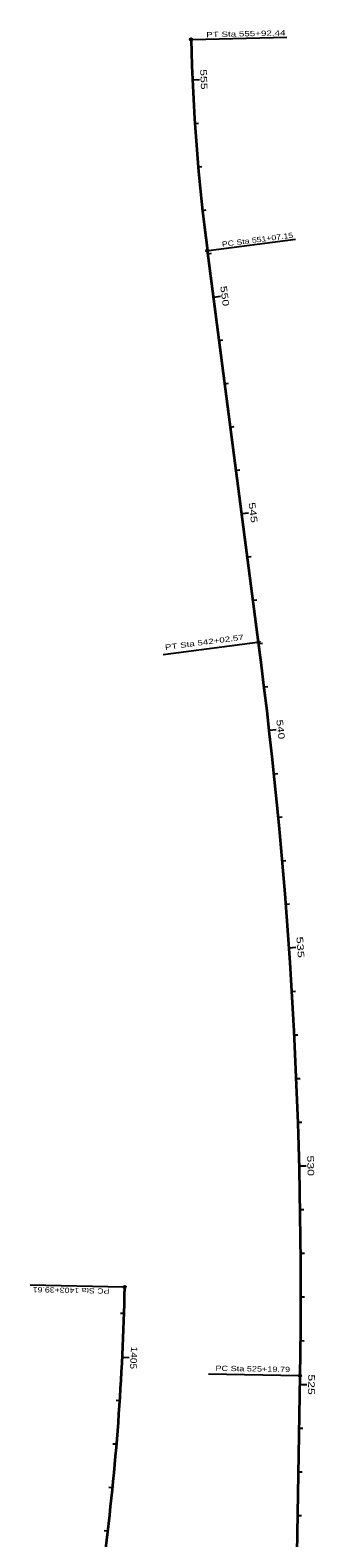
# Model space of a CAD drawing. Extents: x 771045 to 775849, y 632284 to 641017.
# Drawn here: x 772467 to 773120, y 637565 to 641017 of the extents above; entities that cross this region are included whole.
import ezdxf
from ezdxf.enums import TextEntityAlignment as Align

# ---------------------------------------------------------------- set-up
doc = ezdxf.new("R2010")
doc.units = 0
doc.header["$LTSCALE"] = 4.8
for name, color, linetype, lineweight in [('1', 7, 'Continuous', 35), ('30', 7, 'Continuous', 25), ('33', 7, 'Continuous', 25)]:
    doc.layers.add(name, color=color, linetype=linetype, lineweight=lineweight)

msp = doc.modelspace()

# ---------------------------------------------------------------- linework, layer by layer
at = {"layer": '1'}
msp.add_line((772990.84, 639614.773), (772873.465, 640511.706), dxfattribs=at)
msp.add_lwpolyline([(773099.539, 637303.776), (773075.542, 637304.177), (773086.114, 637936.209)], dxfattribs=at)
for centre, radius, start, end in [((777418.376, 641106.467), 4583.662, 181.38943, 187.45554), ((761628.561, 638127.87), 11459.156, 359.04165, 7.45554), ((766955.847, 638255.612), 5729.578, 352.63444, 358.83333)]:
    msp.add_arc(centre, radius, start, end, dxfattribs=at)
at = {"layer": '30'}
for p, q in [((772839.234, 640902.943), (772855.218, 640903.654)), ((772844.764, 640803.098), (772853.245, 640803.661)), ((772852.47, 640703.398), (772860.937, 640704.145)), ((772862.35, 640603.889), (772870.798, 640604.821)), ((772874.392, 640504.619), (772882.82, 640505.721)), ((772887.368, 640405.464), (772903.232, 640407.54)), ((772900.343, 640306.309), (772908.772, 640307.412)), ((772913.319, 640207.155), (772921.747, 640208.258)), ((772926.295, 640108), (772934.723, 640109.103)), ((772939.27, 640008.846), (772947.699, 640009.949)), ((772952.246, 639909.691), (772968.111, 639911.767)), ((772965.222, 639810.537), (772973.65, 639811.639)), ((772978.197, 639711.382), (772986.626, 639712.485)), ((772991.173, 639612.227), (772999.601, 639613.328)), ((773003.693, 639513.015), (773012.131, 639514.042)), ((773015.348, 639413.696), (773031.247, 639415.492)), ((773026.135, 639314.28), (773034.589, 639315.16)), ((773036.054, 639214.774), (773044.516, 639215.58)), ((773045.105, 639115.184), (773053.573, 639115.917)), ((773053.286, 639015.52), (773061.761, 639016.178)), ((773060.597, 638915.788), (773076.559, 638916.888)), ((773067.038, 638815.996), (773075.522, 638816.506)), ((773072.607, 638716.151), (773081.096, 638716.588)), ((773077.305, 638616.262), (773085.797, 638616.624)), ((773081.131, 638516.336), (773089.626, 638516.624)), ((773084.085, 638416.38), (773100.08, 638416.782)), ((773086.166, 638316.402), (773094.665, 638316.541)), ((773087.375, 638216.409), (773095.875, 638216.475)), ((773087.712, 638116.41), (773096.212, 638116.402)), ((772682.689, 638078.583), (772674.193, 638078.846)), ((773087.175, 638016.412), (773095.675, 638016.329)), ((772678.727, 637978.663), (772694.708, 637977.89)), ((773085.783, 637916.422), (773101.781, 637916.154)), ((772673.022, 637878.827), (772664.54, 637879.386)), ((773084.111, 637816.436), (773092.61, 637816.294)), ((772665.576, 637779.106), (772657.105, 637779.813)), ((773082.438, 637716.45), (773090.937, 637716.307)), ((772656.39, 637679.53), (772647.933, 637680.385)), ((773080.766, 637616.464), (773089.265, 637616.321)), ((772645.467, 637580.13), (772637.027, 637581.132))]:
    msp.add_line(p, q, dxfattribs=at)
at = {"layer": '33'}
for p, q in [((772838.761, 640995.389), (773055.941, 641000.657)), ((772876.142, 640512.056), (773075.388, 640538.13)), ((772988.163, 639614.423), (772772.521, 639586.203)), ((772681.537, 638139.008), (772467.409, 638143.369)), ((773083.415, 637936.254), (772876.357, 637939.718))]:
    msp.add_line(p, q, dxfattribs=at)
for centre in [(772836.061, 640995.324), (772873.465, 640511.706), (772990.84, 639614.773), (772684.237, 638138.953), (773086.114, 637936.209)]:
    msp.add_circle(centre, 2.7, dxfattribs=at)

# ---------------------------------------------------------------- texts
at = {"layer": '30'}
for s, rotation, width, p in [('555', 272.545, 1.4, (772857.931, 640903.441)), ('550', 277.456, 1.4, (772906.037, 640406.917)), ('545', 277.456, 1.4, (772970.915, 639911.144)), ('540', 276.443, 1.35, (773034.025, 639414.953)), ('535', 273.943, 1.45, (773079.288, 638916.558)), ('530', 271.443, 1.4, (773102.784, 638416.661)), ('1405', 267.229, 1.15, (772697.388, 637977.396)), ('525', 269.042, 1.4, (773104.479, 637915.983))]:
    msp.add_text(s, height=15, rotation=rotation, dxfattribs=dict(at, width=width)).set_placement(p, align=Align.CENTER)
at = {"layer": '33'}
for s, rotation, width, p in [('PT Sta 555+92.44', 1.389, 1.4, (772870.954, 641000.171)), ('PC Sta 551+07.15', 7.456, 1.25, (772907.65, 640520.213)), ('PT Sta 542+02.57', 7.456, 1.4, (772777.186, 639597.637)), ('PC Sta 1403+39.61', 178.833, 1.25, (772649.163, 638135.667)), ('PC Sta 525+19.79', 359.042, 1.3, (772892.02, 637947.379))]:
    msp.add_text(s, height=12, rotation=rotation, dxfattribs=dict(at, width=width)).set_placement(p)

doc.saveas('drawing.dxf')
